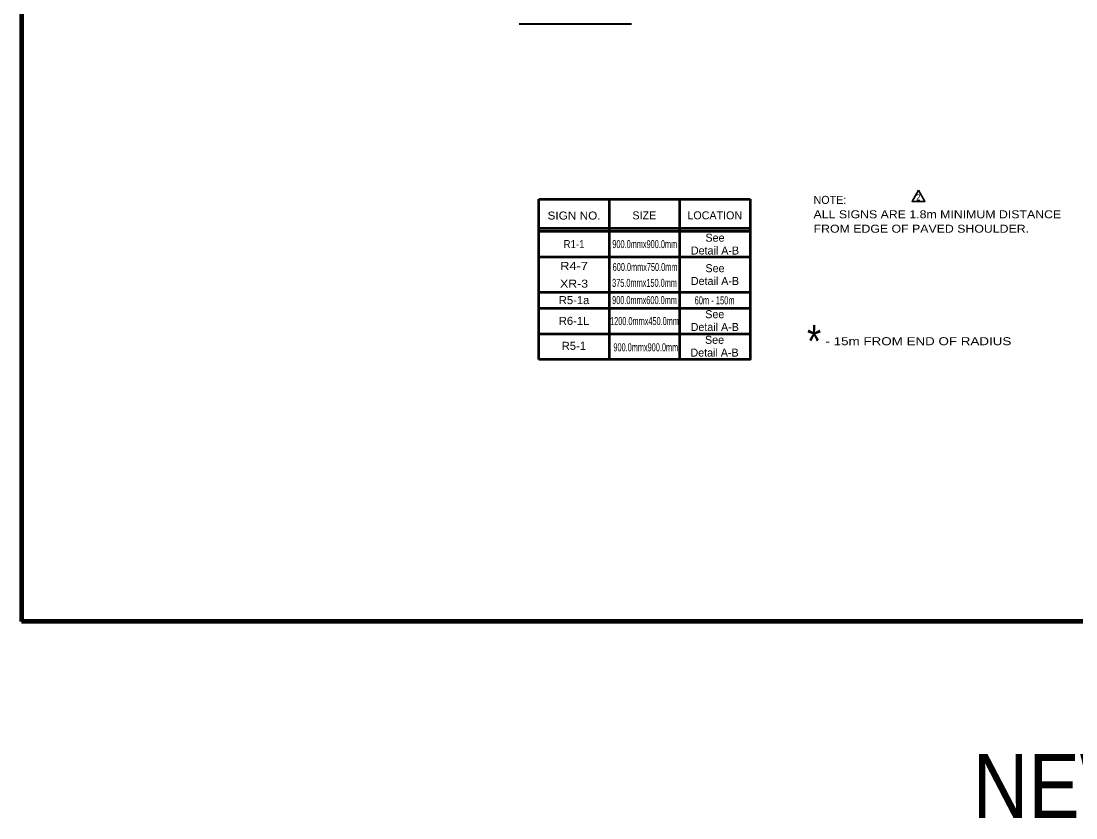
# Model space of a CAD drawing. Extents: x 1081 to 1936, y -630 to -24.
# Drawn here: x 1137.9 to 1533.1, y -629.9 to -331.3 of the extents above; entities that cross this region are included whole.
import ezdxf
from ezdxf.enums import TextEntityAlignment as Align

# ---------------------------------------------------------------- set-up
doc = ezdxf.new("R2010")
doc.units = 0
doc.layers.add('1', color=7, linetype='Continuous', lineweight=53)

msp = doc.modelspace()

# ---------------------------------------------------------------- linework, layer by layer
at = {"layer": '1', "lineweight": 40}
msp.add_line((1324.496, -332.374), (1366.664, -332.374), dxfattribs=at)
at = {"layer": '1'}
for p, q in [((1331.914, -410.1), (1331.914, -398.1)), ((1358.314, -458.1), (1358.314, -398.1)), ((1384.714, -458.1), (1384.714, -398.1)), ((1331.914, -408.9), (1411.114, -408.9)), ((1331.914, -410.1), (1411.114, -410.1)), ((1331.914, -419.7), (1331.914, -410.1)), ((1331.914, -419.7), (1411.114, -419.7)), ((1331.914, -432.9), (1331.914, -419.7)), ((1331.914, -432.9), (1411.114, -432.9)), ((1331.914, -438.9), (1331.914, -432.9)), ((1331.914, -438.9), (1411.114, -438.9)), ((1331.914, -448.5), (1411.114, -448.5))]:
    msp.add_line(p, q, dxfattribs=at)
at = {"layer": '1', "lineweight": 158}
msp.add_line((1929.57, -556.37), (1137.97, -556.37), dxfattribs=at)
msp.add_lwpolyline([(1929.57, -30.27), (1137.87, -30.37), (1137.97, -556.37)], dxfattribs=at)
at = {"layer": '1', "lineweight": 35}
msp.add_lwpolyline([(1474.182, -394.726), (1471.782, -398.882), (1476.582, -398.882)], close=True, dxfattribs=at)
at = {"layer": '1'}
for points in [[(1411.114, -398.1), (1411.114, -458.1), (1331.914, -458.1)], [(1331.914, -398.1), (1358.314, -398.1), (1384.714, -398.1), (1411.114, -398.1)], [(1331.914, -458.1), (1331.914, -448.5), (1331.914, -438.9)]]:
    msp.add_lwpolyline(points, dxfattribs=at)

# ---------------------------------------------------------------- texts
msp.add_text('NOTE:', height=3, dxfattribs=at).set_placement((1434.836, -399.823))
for s, height, width, p in [('2', 2.4, 0.9, (1474.085, -398.554)), ('SIGN NO.', 3, 1.1, (1345.081, -405.697)), ('R1-1', 3, 0.9, (1345.081, -416.394)), ('900.0mmx900.0mm', 3, 0.6, (1371.57, -416.394)), ('R4-7', 3, 1.2, (1345.081, -424.578)), ('600.0mmx750.0mm', 3, 0.6, (1371.691, -424.981)), ('XR-3', 3, 1.15, (1345.081, -431.223)), ('375.0mmx150.0mm', 3, 0.6, (1371.49, -430.921)), ('R5-1a', 3, 1.05, (1345.081, -437.381)), ('900.0mmx600.0mm', 3, 0.6, (1371.49, -437.381)), ('60m - 150m', 3, 0.7, (1397.751, -437.463)), ('R6-1L', 3, 1.05, (1345.081, -445.16)), ('1200.0mmx450.0mm', 3, 0.6, (1371.489, -445.241)), ('*', 12, 0.85, (1435.034, -457.272)), ('- 15m FROM END OF RADIUS', 3, 1.25, (1474.13, -452.789)), ('R5-1', 3, 1.05, (1344.999, -454.519)), ('900.0mmx900.0mm', 3, 0.6, (1371.973, -455.068)), ('NEW', 24, 0.9, (1528.172, -629.936))]:
    msp.add_text(s, height=height, dxfattribs=dict(at, width=width)).set_placement(p, align=Align.CENTER)
for s, p in [('SIZE', (1371.409, -405.616)), ('LOCATION', (1397.816, -405.616)), ('See', (1397.898, -413.994)), ('Detail A-B', (1397.898, -418.794)), ('See', (1397.898, -425.419)), ('Detail A-B', (1397.898, -430.219)), ('See', (1397.815, -442.659)), ('Detail A-B', (1397.815, -447.459)), ('See', (1397.733, -452.264)), ('Detail A-B', (1397.733, -457.064))]:
    msp.add_text(s, height=3, dxfattribs=at).set_placement(p, align=Align.CENTER)
at = {"layer": '1', "width": 1.15}
for s, p in [('ALL SIGNS ARE 1.8m MINIMUM DISTANCE', (1434.836, -405.223)), ('FROM EDGE OF PAVED SHOULDER.', (1434.836, -410.623))]:
    msp.add_text(s, height=3, dxfattribs=at).set_placement(p)

doc.saveas('drawing.dxf')
